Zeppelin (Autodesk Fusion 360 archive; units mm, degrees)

design "Zeppelin" references "Gemfan Hurricane 51466", "TURNIGY_1811"
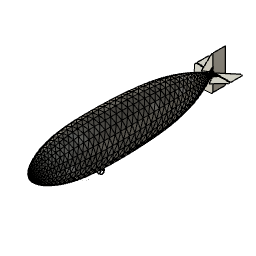
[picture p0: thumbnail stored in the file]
parameter "untereSeiteDreieck" = 220
parameter "kleinerSchnittDreieck" = 18.3138
parameter "untereKante" = 220
base_mesh_feature "Grundnetzelement2"
convert_mesh "Netz konvertieren2" bodies "Envelope"
base_mesh_feature "Grundnetzelement3"
convert_mesh "Netz konvertieren3"
base_mesh_feature "Grundnetzelement4"
convert_mesh "Netz konvertieren4" bodies "Motorhalterung 1"
base_mesh_feature "Grundnetzelement5"
convert_mesh "Netz konvertieren5" bodies "Motorhalterung 2"
base_mesh_feature "Grundnetzelement6"
convert_mesh "Netz konvertieren6" bodies "CFK Connector Vorne"
sketch "Skizze3" plane through (0, 0, 0) normal (1, 0, 0) x axis (0, 1, 0)
  line L1 (0, -276.3) -> (0, -276.5)
  arc A1 centre (-367.7637, 12.4238) radius 430.2363 clockwise from (-307, -413.5) to (-706.3403, -253.0365)
  point P4 (-706.3403, -253.0365)
  point P5 (-307, -413.5)
  vertical L1
  dimension "d6" distance P4 P5 = 430.3733
move "Verschieben4"
work_plane "Arbeitsebene"
sketch "Skizze4" plane through (-63.2811, -308.4675, -275.8442) normal (0.8958, 0.164, 0.413) x axis (-0.1801, 0.9836, 0)
  arc A1 centre (-148.0381, 955.7619) radius 967.1588 clockwise from (0, 0) to (-400, 22)
  point P1 (0, 0)
  point P2 (0, 0)
  coincident P1 P2
pipe "Leitung2" SectionSize 1 SectionThickness 0.25 bodies "CFK Motor Oben 1"
pipe "Leitung3" SectionSize 1 SectionThickness 0.25 bodies "CFK Motor Unten"
mirror "Spiegeln" mirrorStitchTolerance 0.1 bodies "CFK Motor Oben 2"
component_insert "Komponente einfügen1"
component_insert "Komponente einfügen2"
base_mesh_feature "Grundnetzelement8"
convert_mesh "Netz konvertieren7" bodies "ruderhalter_2"
base_mesh_feature "Grundnetzelement9"
convert_mesh "Netz konvertieren8"
move "Verschieben5"
move "Verschieben6"
base_mesh_feature "Grundnetzelement10"
convert_mesh "Netz konvertieren9" bodies "ruderhorn"
base_mesh_feature "Grundnetzelement11"
convert_mesh "Netz konvertieren10" bodies "rudergelenk"
copy_paste_bodies "Körper kopieren/einfügen1"
move "Verschieben7"
copy_paste_bodies "Körper kopieren/einfügen2"
move "Verschieben8"
copy_paste_bodies "Körper kopieren/einfügen3"
move "Verschieben9"
sketch "Skizze5" plane through (0, 0, 0) normal (1, 0, 0) x axis (0, 1, 0)
  line L1 (1250.7758, -2.2569) -> (1250.7758, 0.2431)
  circle C1 centre (1250.7758, -1.0069) radius 1.25
  point P4 (1250.7758, -1.0069)
  point P3 (1250.7758, -2.2569)
  vertical L1
  midpoint L1 P4
  coincident P3 C1
extrude "Extrusion1" new body sketch "Skizze5" distance 200 bodies "CFK Ruderhalter_2"
sketch "Skizze6" plane through (0, 0, -2.5169) normal (0, 0, 1) x axis (-1, 0, 0)
  line L1 (11.8094, -1246.2725) -> (41.4821, -1194.878)
  line L2 (251.951, -1246.2725) -> (11.8094, -1246.2725)
  line L3 (18, -1246.2725) -> (80, -1246.2725)
  line L4 (101.8095, -1090.3879) -> (11.8094, -1246.2725)
  line L5 (218, -1246.2725) -> (11.8094, -1246.2725)
  line L6 (101.8095, -1090.3879) -> (251.951, -1246.2725)
  line L7 (-35, -1218.4724) -> (-32.9972, -1218.4724)
  line L8 (-35, -1213.6225) -> (-35, -1218.4724)
  line L9 (-41, -1213.6225) -> (-35, -1213.6225)
  line L10 (-41, -1218.4724) -> (-41, -1213.6225)
  line L11 (-44.5, -1218.4724) -> (-41, -1218.4724)
  line L12 (-44.5, -1224.7646) -> (-44.5, -1218.4724)
  line L13 (-45, -1225.3606) -> (-44.5, -1224.7646)
  line L14 (-52, -1225.3606) -> (-45, -1225.3606)
  line L15 (-52, -1246.2725) -> (-52, -1225.3606)
  line L16 (-251.9509, -1246.2725) -> (-52, -1246.2725)
  line L17 (-101.8096, -1090.388) -> (-27.8597, -1218.4724)
  line L18 (-251.9509, -1246.2725) -> (-101.8096, -1090.388)
  line L19 (-52, -1225.3606) -> (-45, -1225.3606)
  line L20 (-45, -1225.3606) -> (-44.5, -1224.7646)
  line L21 (-44.5, -1218.4724) -> (-41, -1218.4724)
  line L22 (-41, -1213.6225) -> (-35, -1213.6225)
  line L23 (-35, -1218.4724) -> (-27.8597, -1218.4724)
  line L24 (-41.4821, -1194.878) -> (-27.8597, -1218.4724)
  line L25 (-80, -1246.2725) -> (-52, -1246.2725)
  line L26 (200, -1249.5258) -> (200, -1252.0258)
  line L27 (-200, -1252.0258) -> (-200, -1249.5258)
  line L28 (-200, -1249.5258) -> (200, -1249.5258)
  line L29 (-44.5, -1218.4724) -> (-44.5, -1224.7646)
  line L30 (-41, -1213.6225) -> (-41, -1218.4724)
  line L31 (-35, -1213.6225) -> (-35, -1218.4724)
  line L32 (-231.8093, -1254.8215) -> (-11.8093, -1254.8215)
  line L33 (-231.8093, -1414.8215) -> (-231.8093, -1254.8215)
  line L34 (-27.8597, -1218.4724) -> (-11.8093, -1246.2725)
  line L35 (-11.8093, -1246.2725) -> (-52, -1246.2725)
  line L36 (-231.8093, -1225.3605) -> (-231.8093, -1246.2725)
  line L37 (231.8094, -1225.3605) -> (231.8094, -1246.2725)
  line L38 (-44.4083, -1254.8215) -> (-41.4083, -1254.8215)
  line L39 (-231.8093, -1414.8215) -> (-199.7764, -1414.8215)
  line L40 (-11.8093, -1254.8215) -> (-199.7764, -1414.8215)
  line L41 (0, -20) -> (0, -2.5)
  line L42 (231.8093, -1254.8215) -> (11.8093, -1254.8215)
  line L43 (231.8093, -1414.8215) -> (231.8093, -1254.8215)
  line L44 (11.8093, -1254.8215) -> (199.7764, -1414.8215)
  line L45 (231.8093, -1414.8215) -> (199.7764, -1414.8215)
  point P3 (11.8094, -1246.2725)
  point P4 (11.8094, -1246.2725)
  point P21 (-27.8597, -1218.4724)
  point P22 (-101.8096, -1090.388)
  point P23 (-251.9509, -1246.2725)
  point P37 (200, -1249.5258)
  point P40 (200, -1249.5258)
  point P38 (-200, -1249.5258)
  point P41 (-200, -1249.5258)
  point P20 (-251.9509, -1246.2725)
  point P31 (-27.8597, -1218.4724)
  point P46 (-27.8597, -1218.4724)
  point P45 (-11.8093, -1246.2725)
  point P34 (-52, -1246.2725)
  point P47 (-52, -1246.2725)
  point P48 (-231.8093, -1246.2725)
  point P49 (-231.8093, -1225.3605)
  point P50 (231.8094, -1246.2725)
  point P51 (231.8094, -1225.3605)
  point P42 (-11.8093, -1254.8215)
  point P43 (-231.8093, -1254.8215)
  point P52 (-231.8093, -1254.8215)
  point P58 (11.8093, -1254.8215)
  point P60 (231.8093, -1254.8215)
  point P44 (-231.8093, -1414.8215)
  point P61 (231.8093, -1414.8215)
  point P59 (231.8093, -1254.8215)
  point P55 (-199.7764, -1414.8215)
  point P62 (199.7764, -1414.8215)
  point P8 (101.8095, -1090.3879)
  point P18 (-52, -1225.3606)
  point P19 (-52, -1246.2725)
  coincident P3 P4
  collinear L2 L3
  horizontal L5
  horizontal L7
  horizontal L9
  horizontal L14
  coincident L7 P21
  coincident L17 P22
  coincident L16 P23
  collinear L14 L19
  collinear L13 L20
  collinear L11 L21
  collinear L9 L22
  collinear L7 L23
  collinear L17 L24
  collinear L16 L25
  coincident P37 P40
  coincident P38 P41
  coincident P20 P23
  collinear L12 L29
  collinear L10 L30
  collinear L8 L31
  parallel L28 L32
  vertical L33
  coincident P31 P46
  horizontal P4 P45
  coincident P34 P47
  perpendicular L15 L35
  collinear L1 L4
  coincident L16 P48
  coincident L18 P49
  perpendicular L16 L36
  coincident L2 P50
  coincident L6 P51
  perpendicular L2 L37
  vertical P42 P45
  collinear L32 L38
  coincident P43 P52
  perpendicular L33 L39
  symmetric P42 L41 P58
  symmetric P43 L41 P60
  symmetric P44 L41 P61
  symmetric P52 L41 P59
  symmetric P55 L41 P62
  dimension "LinkeSeiteUnten" distance P43 P44 = 160
  dimension "d55" angle L17 L34 = 180
  dimension "eineSeiteDreieck" distance P22 P45 = 180
  dimension "d61" distance P4 P8 = 180 (= "eineSeiteDreieck")
  dimension "d71" distance P45 L36 = 220 (= "untereKante")
  dimension "AbschnittDreieck" distance P48 P49 = 20.912
  dimension "d74" distance P4 L37 = 220 (= "untereKante")
  dimension "d75" distance P50 P51 = 20.912 (= "AbschnittDreieck")
  dimension "d76" distance P18 P19 = 20.9119
  dimension "d77" distance P42 P52 = 220 (= "untereKante")
  dimension "d78" distance P44 P55 = 32.0329
extrude "Extrusion2" new body sketch "Skizze6" profile of L1 L2 L3 L4 L6 L7 L8 L9 L10 L11 L12 L13 L14 L15 L16 L17 L18 L19 L20 L21 L22 L23 L24 L25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 along normal blind 3 bodies "Depron R2-L", "Depron R2-R"
sketch "Skizze7" plane through (-3, 0, 0) normal (1, 0, 0) x axis (0, 1, 0)
  line L1 (1241.7614, 232.081) -> (1241.7614, 12.081)
  line L2 (1085.8768, 102.081) -> (1241.7614, 12.081)
  line L3 (1231.039, 18.2716) -> (1190.3668, 41.7537)
  line L4 (1241.7614, 18.2716) -> (1241.7614, 80.2716)
  line L5 (1220.8494, 232.081) -> (1241.7614, 232.081)
  line L6 (1085.8768, 102.081) -> (1220.8494, 232.081)
  line L7 (22.5, 0) -> (1.75, 0)
  line L8 (1220.8494, -232.081) -> (1241.7614, -232.081)
  line L9 (1085.8768, -102.081) -> (1220.8494, -232.081)
  line L10 (1241.7614, -232.081) -> (1241.7614, -12.081)
  line L11 (1085.8768, -102.081) -> (1241.7614, -12.081)
  line L12 (1241.7614, 80.2716) -> (1237.7614, 19.0092)
  line L13 (1237.7614, 72.2751) -> (1241.7614, 80.2716)
  line L14 (1237.7614, 19.0092) -> (1237.7614, 72.2751)
  line L15 (1414.7614, 232.081) -> (1244.7614, 232.081)
  line L16 (1414.7614, -232.081) -> (1414.7614, 232.081)
  line L17 (1244.7614, -232.081) -> (1244.7614, 232.081)
  line L18 (1414.7614, -232.081) -> (1244.7614, -232.081)
  line L19 (1258, -50.7284) -> (1244.7614, -50.7284)
  line L20 (1258, 12.081) -> (1258, -50.7284)
  line L21 (1244.7614, 12.081) -> (1258, 12.081)
  point P2 (1241.7614, 12.081)
  point P15 (1241.7614, -12.081)
  point P3 (1241.7614, 232.081)
  point P12 (1241.7614, -232.081)
  point P4 (1085.8768, 102.081)
  point P14 (1085.8768, -102.081)
  point P9 (1220.8494, 232.081)
  point P13 (1220.8494, -232.081)
  point P21 (1414.7614, -232.081)
  point P19 (1244.7614, 232.081)
  point P23 (1244.7614, -50.7284)
  point P26 (1244.7614, 12.081)
  point P27 (1237.7614, -50.7284)
  point P20 (1414.7614, 232.081)
  point P24 (1258, -50.7284)
  vertical L1
  collinear L2 L3
  collinear L1 L4
  perpendicular L1 L5
  symmetric P2 L7 P15
  symmetric P3 L7 P12
  symmetric P4 L7 P14
  symmetric P9 L7 P13
  perpendicular L1 L15
  perpendicular L15 L16
  horizontal P12 P21
  horizontal P3 P19
  perpendicular L15 L17
  perpendicular L17 L18
  coincident L17 P23
  perpendicular L17 L19
  perpendicular L19 L20
  coincident L17 P26
  perpendicular L17 L21
  horizontal P23 P27
  horizontal P2 P26
  dimension "d79" distance P2 P3 = 220 (= "untereKante")
  dimension "d80" distance P2 P4 = 180 (= "eineSeiteDreieck")
  dimension "d81" distance P3 P9 = 20.912 (= "AbschnittDreieck")
  dimension "kurzeSeiteViereck" distance P19 P20 = 170
  dimension "d85" distance P3 P19 = 3
  dimension "servolaenge" distance P23 P24 = 13.2386
extrude "Extrusion3" new body sketch "Skizze7" profile of L1 L2 L3 L4 L5 L6 L8 L9 L10 L11 L15 L16 L17 L18 L19 L20 L21 along normal blind 3
move "Verschieben10"
extrude "Extrusion4" add of existing geometry blind 0.2
extrude "Extrusion5" add of existing geometry blind 0.2
extrude "Extrusion6" add of existing geometry blind 0.6
extrude "Extrusion7" cut of existing geometry blind -0.4
extrude "Extrusion8" add of existing geometry blind 2
offset_faces "Flächen versetzen" distance -0.3
extrude "Extrusion10" add of existing geometry blind 0.2
extrude "Extrusion11" add of existing geometry blind 0.2
extrude "Extrusion12" add of existing geometry blind 0.2
extrude "Extrusion13" add of existing geometry blind 0.2
extrude "Extrusion14" add of existing geometry blind 0.6
extrude "Extrusion15" cut of existing geometry blind -0.4
move_face "Fläche verschieben1" RotateAngle -5
extrude "Extrusion18" add of existing geometry blind 2.6
extrude "Extrusion19" add of existing geometry blind 2.6
move_face "Fläche verschieben2"
extrude "Extrusion20" add of existing geometry blind 3
extrude "Extrusion21" cut of existing geometry blind -2.6
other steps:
base_feature "Basiselement2" bodies "rudergelenk", "rudergelenk (1)"
base_feature "Basiselement3" bodies "rudergelenk (1)", "rudergelenk (1) (1)"
base_feature "Basiselement4" bodies "rudergelenk (2)"
named bodies: "Envelope", "Motorhalterung 1", "Motorhalterung 2", "CFK Connector Vorne", "CFK Motor Oben 1", "CFK Motor Unten", "CFK Motor Oben 2", "ruderhalter_2", "ruderhalter_1", "CFK Ruderhalter_2", "Depron R2-L", "Depron R2-R", "ruderhorn", "rudergelenk", "rudergelenk (1)", "rudergelenk (1) (1)", "rudergelenk (2)"

design "Gemfan Hurricane 51466"
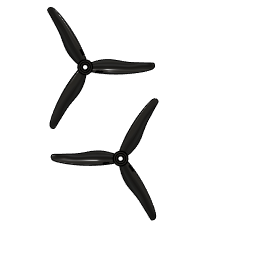
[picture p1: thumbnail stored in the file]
sketch "Sketch1" plane through (0, 0, 0) normal (0, 1, 0) x axis (1, 0, 0)
  curve K1 (5.4694, -4.0404) -> (5.1621, 4.4263)
  curve K2 (26.4739, 6.387) -> (10.3147, 5.303)
  curve K3 (55.5282, 3.9374) -> (37.5729, 6.2078)
  curve K4 (23.3421, -7.4304) -> (38.5067, -4.4448)
  curve K5 (7.6655, -5.2742) -> (22.2218, -7.6881)
  curve K6 (52.69, -3.7559) -> (67.3074, -3.2468)
  curve K7 (66.947, -7.3026) -> (59.4681, 7.5356)
  curve K8 (66.2975, -0.0581) -> (55.4147, 4.071)
  line L1 (78.7648, 0) -> (0, 0)
  curve K9 (61.3404, -6.2574) -> (65.9163, 0.3238)
  curve K10 (8.9395, 5.261) -> (1.3848, 3.5917)
  circle C1 centre (0, 0) radius 6.8
  circle C2 centre (0, 0) radius 2.5
  point P1 (0, 0)
  point P2 (0, 0)
  point P3 (0, 0)
  point P4 (5.1621, 4.4263)
  point P14 (5.4694, -4.0404)
  point P5 (18.3943, 5.845)
  point P6 (46.5505, 5.0726)
  point P12 (30.9244, -5.9376)
  point P13 (14.9437, -6.4811)
  point P10 (59.9987, -3.5013)
  point P8 (63.2076, 0.1165)
  point P7 (60.8561, 2.0065)
  point P29 (0, 0)
  point P9 (63.6284, -2.9668)
  coincident P1 P2
  coincident P1 P3
  coincident C1 P4
  coincident C1 P14
  midpoint P5 K2
  midpoint P6 K3
  midpoint P12 K4
  midpoint P13 K5
  midpoint P10 K6
  midpoint P8 K7
  midpoint P7 K8
  coincident P1 P29
  midpoint P9 K9
  midpoint P4 K10
  dimension "d1" diameter C1 = 13.6
  dimension "d2" diameter C2 = 5
extrude "Extrude1" new body sketch "Sketch1" profile of C1 C2 distance 7
work_plane "WorkPlane6" AlongDistance 4.5
sketch "Sketch3" plane through (4.5, 0, 0) normal (1, 0, 0) x axis (0, 0, -1)
  line L1 (6.8, -3.5) -> (-6.8, -3.5)
  line L2 (-6.8, 3.5) -> (6.8, 3.5)
  line L3 (4, -3.5) -> (4, 3.5)
  line L4 (-3.75, -3.5) -> (-3.75, 3.5)
  curve K1 (-3.75, -3.1239) -> (-3.75, -3.1239)
  curve K2 (-3.5611, -3.317) -> (-3.9389, -2.9308)
  curve K3 (0.2448, -0.7564) -> (-2.2448, -2.2436)
  curve K4 (-3.5886, -0.8664) -> (-0.9748, 1.9804)
  curve K5 (3.4341, 3.3087) -> (4.5659, 2.0069)
  curve K6 (0.0208, 2.5606) -> (2.6178, 3.2817)
  point P7 (4, 3.5)
  point P9 (-3.75, 3.5)
  point P11 (-3.75, -3.1239)
  point P14 (4, 2.6578)
  point P12 (-1, -1.5)
  point P16 (-2.2817, 0.557)
  point P15 (1.3193, 2.9212)
  point P1 (0, 0)
  vertical L3
  coincident L2 P7
  vertical L4
  coincident L2 P9
  coincident L4 P11
  coincident L3 P14
  midpoint P11 K2
  midpoint P12 K3
  midpoint P16 K4
  midpoint P14 K5
  midpoint P15 K6
  dimension "d15" distance P1 L3 = 4
  dimension "d17" distance P1 L4 = 3.75
work_plane "WorkPlane4" AlongDistance 22
sketch "Sketch5" plane through (22, 0, 0) normal (1, 0, 0) x axis (0, 0, -1)
  line L1 (6.0622, 0) -> (-7.0278, 0)
  curve K1 (-4.0404, 0) -> (4.4263, 0)
  line L2 (-7.0278, -3) -> (-7.0278, 0)
  line L3 (6.0622, 3.7) -> (6.0622, 0)
  curve K2 (-7.0278, -3) -> (-7.0278, -3)
  curve K3 (-6.9778, -3.0682) -> (-7.0777, -2.9318)
  point P4 (0, 0)
  point P2 (-7.0278, 0)
  point P7 (-7.0278, -3)
  horizontal L1
  coincident L1 P4
  coincident P2 K1
  perpendicular L1 L2
  midpoint P7 K3
sketch "Sketch8" plane through (22, 0, 0) normal (1, 0, 0) x axis (0, 0, -1)
  curve K1 (-2.9668, 0) -> (-3.75, -3.1239)
  curve K2 (-4.0148, -0.0865) -> (-4.1879, -1.0525)
  curve K3 (0.1695, 0.6998) -> (-6.1031, -0.6998)
  curve K4 (-2.9668, 0) -> (4, 2.6578)
  point P2 (-3.75, -3.1239)
  point P5 (-3.75, -3.1239)
  point P3 (-7.0278, -3)
  point P6 (-7.0278, -3)
  point P4 (-2.9668, 0)
  point P7 (-2.9668, 0)
  point P10 (-4.1014, -0.5695)
  point P9 (4, 2.6578)
  point P17 (4, 2.6578)
  point P8 (6.0622, 3.7)
  point P18 (6.0622, 3.7)
  coincident P2 P5
  coincident P3 P6
  coincident P4 P7
  midpoint P10 K2
  midpoint P4 K3
  coincident P9 P17
  coincident P8 P18
loft "Loft1" sketch "Sketch3" + "Sketch5"
sketch "Sketch20" plane through (0, 0, 0) normal (0, 0, 1) x axis (1, 0, 0)
  curve K1 (63.6284, 0) -> (4.5, 2.6578)
  curve K2 (63.6284, 0) -> (4.5, -3.1239)
  line L1 (4.5, -3.1239) -> (4.5, 2.6578)
  curve K3 (63.832, 0.4996) -> (4.5, 2.6578)
  curve K4 (23.1023, 5.0891) -> (6.2355, 3.4227)
  curve K5 (5.6102, 3.6045) -> (3.3898, 1.711)
  curve K6 (32.3804, 4.5964) -> (22.8999, 4.8276)
  curve K7 (64.042, 1.479) -> (50.2693, 3.2872)
  curve K8 (64.0517, -0.4301) -> (63.6123, 1.4292)
  line L2 (6.8, -3.5) -> (-6.8, -3.5)
  line L3 (-6.8, 3.5) -> (6.8, 3.5)
  line L4 (6.8, 3.3093) -> (6.8, 3.5)
  line L5 (6.8, -3.5) -> (6.8, -3.2734)
  line L6 (0, 3.5) -> (0, -3.5)
  line L7 (6.8, -3.5) -> (0, -3.5)
  line L8 (0, 3.5) -> (6.8, 3.5)
  point P2 (4.5, 2.6578)
  point P6 (4.5, 2.6578)
  point P4 (4.5, -3.1239)
  point P7 (4.5, -3.1239)
  point P8 (4.5, 2.6578)
  point P12 (63.832, 0.4996)
  point P9 (14.6689, 4.2559)
  point P10 (27.6402, 4.712)
  point P11 (57.1557, 2.3831)
  point P25 (6.8, 3.5)
  point P27 (6.8, 3.5)
  point P28 (6.8, 3.3093)
  point P29 (6.8, -3.2734)
  point P24 (6.8, -3.5)
  point P30 (6.8, -3.5)
  point P1 (0, 0)
  point P31 (0, -3.5)
  point P33 (6.8, 3.5)
  coincident P2 P6
  coincident P4 P7
  coincident P6 P8
  coincident K1 P12
  midpoint P9 K4
  midpoint P8 K5
  midpoint P10 K6
  midpoint P11 K7
  midpoint P12 K8
  coincident P25 P27
  coincident K3 P28
  perpendicular L3 L4
  coincident K2 P29
  coincident P24 P30
  perpendicular L2 L5
  perpendicular L2 L6
  midpoint P1 L6
  midpoint L2 P31
  coincident P25 P33
revolve "Revolve1" sketch "Sketch20" AlongAngle 360
circular_pattern "C-Pattern1" TotalAngle 360
combine "Combine1"
fillet "Fillet1" radius 0.15 0.2 0.2
chamfer "Chamfer1" distance 1
sketch "Sketch9" plane through (0, 3.5, 0) normal (0, 1, 0) x axis (-1, 0, 0)
  line L1 (2.4871, -1.6776) -> (0, 0)
  line L2 (2.3103, -0.9552) -> (1.7511, -1.7843)
  line L3 (3, 0) -> (0, 0)
  curve K1 (1.8074, 6.3477) -> (-0.2661, 6.5946)
  curve K2 (-6.401, -1.6086) -> (-5.5781, -3.5277)
  curve K3 (4.5936, -4.7391) -> (5.8442, -3.0669)
  circle C1 centre (0, 0) radius 2.5
  circle C2 centre (0, 0) radius 4.75
  circle C3 centre (0, 0) radius 2.5
  circle C4 centre (0, 0) radius 3
  arc A1 centre (2.0707, -1.3967) radius 0.5023 clockwise from (2.3103, -0.9552) to (1.7511, -1.7843)
  arc A2 centre (0, 0) radius 6.6 clockwise from (1.8074, 6.3477) to (5.8442, -3.0669)
  arc A3 centre (0, 0) radius 6.6 clockwise from (-6.401, -1.6086) to (-0.2661, 6.5946)
  arc A4 centre (0, 0) radius 6.6 clockwise from (4.5936, -4.7391) to (-5.5781, -3.5277)
  point P1 (0, 0)
  point P3 (0, 0)
  point P4 (0, 0)
  point P6 (0, 0)
  point P7 (2.4871, -1.6776)
  point P9 (2.3103, -0.9552)
  point P8 (1.7511, -1.7843)
  point P11 (2.0307, -1.3697)
  point P12 (0, 0)
  point P13 (3, 0)
  coincident P1 P3
  concentric C3 C4
  coincident P4 P6
  coincident C4 P7
  coincident P7 A1
  tangent C4 A1
  coincident C1 P9
  coincident C1 P8
  coincident L1 P11
  perpendicular L1 L2
  midpoint P11 L2
  coincident P1 P12
  coincident C4 P13
  horizontal L3
  dimension "d24" diameter C2 = 9.5
  dimension "d25" diameter C4 = 6
  dimension "d26" distance P8 P9 = 1
  dimension "d35" angle L1 L3 = 34
move "Move1" TranslateX 0 TranslateY -0.025 TranslateZ 0
extrude "Extrude2" add sketch "Sketch9" profile of C1 C2 C3 C4 L1 A1 to an object
chamfer "Chamfer2" distance 0.5
extrude "Extrude3" cut sketch "Sketch9" profile of C1 C3 A1 L2 against normal blind 2
circular_pattern "C-Pattern2" TotalAngle 360
fillet "Fillet2" radius 0.1
fillet "Fillet3" radius 0.1
work_plane "WorkPlane7" AlongDistance 8
sketch "Gemfan Logo" plane through (0, 0, 0) normal (0, 1, 0) x axis (1, 0, 0)
  curve K1 (-21.8749, -5.831) -> (-20.1359, 0.6002)
  curve K2 (-24.28, -4.52) -> (-20.6611, -1.3859)
  curve K3 (-23.3443, -4.4717) -> (-25.2158, -4.5684)
  line L1 (-21.0026, -2.6965) -> (-21.8749, -5.831)
  line L2 (-23.7916, -2.6965) -> (-21.0026, -2.6965)
  line L3 (-24.28, -4.52) -> (-23.7916, -2.6965)
  line L4 (-20.6611, -1.3859) -> (-20.1359, 0.6002)
  line L5 (-12.3656, 0.8894) -> (-19.4089, 0.8894)
  curve K4 (28.4771, 4.595) -> (-20.955, -5.8616)
  curve K5 (33.0602, 3.9357) -> (23.894, 5.2543)
  curve K6 (-17.2888, -2.7107) -> (-24.6212, -9.0126)
  curve K7 (25.1622, 1.9813) -> (-20.955, -5.8616)
  line L6 (25.1622, 1.9813) -> (28.4771, 4.595)
  curve K8 (-17.694, -3.4791) -> (-24.2161, -8.2442)
  curve K9 (28.6113, 1.0913) -> (21.713, 2.8713)
  line L7 (-21.2476, -5.8041) -> (-19.4089, 0.8894)
  line L8 (-17.3535, -2.0106) -> (-17.1389, -1.1922)
  line L9 (-16.7225, -2.0106) -> (-17.3535, -2.0106)
  line L10 (-15.8, -1.1922) -> (-17.1389, -1.1922)
  curve K10 (-16.7225, -2.0106) -> (-21.2476, -5.8041)
  curve K11 (-16.0902, -1.5693) -> (-17.3548, -2.4519)
  curve K12 (-12.3656, 0.8894) -> (-15.8, -1.1922)
  curve K13 (-11.9871, 1.0819) -> (-12.7441, 0.6969)
  line L11 (-14.3976, -5.927) -> (-20.4864, -5.927)
  line L12 (-13.9738, -4.1566) -> (-14.3976, -5.927)
  line L13 (-17.6773, -4.1566) -> (-13.9738, -4.1566)
  line L14 (-20.4864, -5.927) -> (-17.6773, -4.1566)
  line L15 (-13.7968, -3.4173) -> (-16.2424, -3.4173)
  line L16 (-13.4588, -2.0058) -> (-13.7968, -3.4173)
  line L17 (-16.2424, -3.4173) -> (-13.4588, -2.0058)
  line L18 (-13.8215, -5.927) -> (-12.7833, -1.7405)
  line L19 (-11.1054, -5.927) -> (-13.8215, -5.927)
  line L20 (-10.1204, -1.9546) -> (-11.1054, -5.927)
  line L21 (-9.7695, -5.9089) -> (-10.1204, -1.9546)
  line L22 (-8.1269, -5.9089) -> (-9.7695, -5.9089)
  line L23 (-5.7331, -2.13) -> (-8.1269, -5.9089)
  line L24 (-6.7309, -5.9089) -> (-5.7331, -2.13)
  line L25 (-4.0148, -5.9089) -> (-6.7309, -5.9089)
  line L26 (-2.2198, 0.8894) -> (-4.0148, -5.9089)
  line L27 (-5.5252, 0.8894) -> (-2.2198, 0.8894)
  line L28 (-8.1349, -2.7437) -> (-5.5252, 0.8894)
  line L29 (-8.3619, -0.1859) -> (-8.1349, -2.7437)
  line L30 (-8.3619, -0.1859) -> (-12.7833, -1.7405)
  line L31 (-3.3335, -5.9313) -> (-1.5326, 0.8894)
  line L32 (-0.5052, -5.9313) -> (-3.3335, -5.9313)
  line L33 (-0.0707, -4.2859) -> (-0.5052, -5.9313)
  line L34 (3.778, -4.2859) -> (-0.0707, -4.2859)
  line L35 (4.3561, -2.0964) -> (3.778, -4.2859)
  line L36 (0.4746, -2.0964) -> (4.3561, -2.0964)
  line L37 (0.6849, -1.3001) -> (0.4746, -2.0964)
  line L38 (4.5664, -1.3001) -> (0.6849, -1.3001)
  line L39 (5.1445, 0.8894) -> (4.5664, -1.3001)
  line L40 (-1.5326, 0.8894) -> (5.1445, 0.8894)
  line L41 (7.4604, 0.8894) -> (3.2005, -5.9313)
  line L42 (12.0969, 0.8894) -> (7.4604, 0.8894)
  line L43 (12.0969, -5.9313) -> (12.0969, 0.8894)
  line L44 (9.2568, -5.9313) -> (12.0969, -5.9313)
  line L45 (9.2568, -4.9008) -> (9.2568, -5.9313)
  line L46 (6.9418, -4.9008) -> (9.2568, -4.9008)
  line L47 (6.2983, -5.9313) -> (6.9418, -4.9008)
  line L48 (3.2005, -5.9313) -> (6.2983, -5.9313)
  line L49 (9.3263, -3.2639) -> (7.7788, -3.2639)
  line L50 (9.3263, -0.7861) -> (9.3263, -3.2639)
  line L51 (7.7788, -3.2639) -> (9.3263, -0.7861)
  line L52 (17.3328, 0.8894) -> (14.2439, 0.8894)
  line L53 (18.2037, -3.0583) -> (17.3328, 0.8894)
  line L54 (19.2029, 0.8894) -> (18.2037, -3.0583)
  line L55 (22.2157, 0.8894) -> (19.2029, 0.8894)
  line L56 (20.4893, -5.9313) -> (22.2157, 0.8894)
  line L57 (17, -5.9313) -> (20.4893, -5.9313)
  line L58 (15.2595, -5.9313) -> (16.1894, -2.2572)
  line L59 (12.5176, -5.9313) -> (15.2595, -5.9313)
  line L60 (14.2439, 0.8894) -> (12.5176, -5.9313)
  line L61 (17, -5.9313) -> (16.1894, -2.2572)
  point P14 (-24.28, -4.52)
  point P24 (28.4771, 4.595)
  point P21 (-20.955, -5.8616)
  point P31 (25.1622, 1.9813)
  point P39 (-16.7225, -2.0106)
  point P20 (-12.3656, 0.8894)
  midpoint P14 K3
  horizontal L2
  horizontal L5
  midpoint P24 K5
  midpoint P21 K6
  midpoint P21 K8
  midpoint P31 K9
  horizontal L9
  horizontal L10
  midpoint P39 K11
  midpoint P20 K13
  collinear L12 L16
  horizontal L13
  horizontal L15
  parallel L18 L20
  horizontal L25
  parallel L24 L26
  parallel L25 L27
  horizontal L19
  horizontal L22
  parallel L21 L29
  equal L23 L28
  collinear L11 L19
  collinear L22 L25
  parallel L26 L31
  horizontal L32
  parallel L31 L33
  parallel L32 L34
  parallel L31 L35
  parallel L34 L36
  parallel L35 L37
  parallel L34 L38
  collinear L35 L39
  horizontal L40
  equal L35 L39
  equal L19 L25
  horizontal L42
  perpendicular L42 L43
  perpendicular L43 L44
  perpendicular L44 L45
  perpendicular L45 L46
  parallel L48 L49
  perpendicular L48 L50
  horizontal L48
  collinear L32 L48
  collinear L44 L48
  parallel L41 L51
  parallel L47 L51
  collinear L40 L42
  collinear L27 L40
  collinear L5 L27
  horizontal L52
  parallel L54 L56
  parallel L52 L57
  parallel L54 L58
  parallel L57 L59
  parallel L58 L60
  collinear L44 L59
  collinear L57 L59
  collinear L42 L52
  collinear L52 L55
  parallel L53 L61
work_plane "WorkPlane8" AlongDistance 10
mirror "Mirror2"
sketch "GEMFAN" plane through (28.9566, 10, -18.6867) normal (0, 1, 0) x axis (1, 0, 0)
  line L1 (-18.9529, -15.1247) -> (-18.6056, -15.0943)
  line L2 (-18.5773, -14.9274) -> (-18.5336, -14.6743)
  line L3 (-17.5691, -14.5537) -> (-18.4462, -14.6304)
  line L4 (-18.1586, -14.9691) -> (-18.1408, -14.8649)
  curve K1 (-18.68, -15.4941) -> (-18.5336, -14.6743)
  curve K2 (-12.5236, -13.6473) -> (-18.5652, -15.4879)
  line L5 (-12.9079, -14.0089) -> (-12.5236, -13.6473)
  curve K3 (-12.9079, -14.0089) -> (-18.5652, -15.4879)
  line L6 (-17.9741, -14.8503) -> (-18.1408, -14.8649)
  curve K4 (-18.0801, -14.9623) -> (-18.6022, -15.484)
  curve K5 (-18.9938, -15.3571) -> (-18.5773, -14.9274)
  line L7 (-18.9938, -15.3571) -> (-18.9529, -15.1247)
  line L8 (-18.6022, -15.484) -> (-18.4462, -14.6304)
  line L9 (-17.2585, -14.8834) -> (-17.1718, -15.372)
  line L10 (-16.0179, -15.2738) -> (-15.9817, -15.0642)
  line L11 (-14.2556, -14.2638) -> (-13.8709, -14.2301)
  line L12 (-15.4543, -14.7433) -> (-15.9377, -14.7856)
  line L13 (-15.5025, -15.0223) -> (-15.4543, -14.7433)
  line L14 (-15.5564, -15.2334) -> (-15.1003, -14.3377)
  line L15 (-14.3962, -15.1319) -> (-14.2556, -14.2638)
  line L16 (-14.0548, -15.1021) -> (-14.3962, -15.1319)
  line L17 (-17.0588, -14.644) -> (-17.5925, -14.8857)
  line L18 (-16.3701, -15.3046) -> (-16.0179, -15.2738)
  line L19 (-13.2629, -14.1769) -> (-13.4036, -15.0451)
  line L20 (-17.5925, -14.8857) -> (-17.6761, -15.4184)
  line L21 (-17.0027, -14.96) -> (-17.0588, -14.644)
  line L22 (-15.4368, -14.6419) -> (-15.3887, -14.3629)
  line L23 (-18.5061, -15.491) -> (-17.7479, -15.4246)
  line L24 (-15.3887, -14.3629) -> (-16.2201, -14.4357)
  curve K6 (-17.5691, -14.5537) -> (-17.9741, -14.8503)
  line L25 (-17.6737, -14.9261) -> (-18.0049, -15.1322)
  line L26 (-18.6056, -15.0943) -> (-18.68, -15.4941)
  line L27 (-17.7479, -15.4246) -> (-17.7144, -15.1995)
  line L28 (-16.9672, -15.3541) -> (-16.7103, -14.8574)
  line L29 (-18.0801, -14.9623) -> (-18.1586, -14.9691)
  line L30 (-14.8135, -15.0391) -> (-15.1018, -15.0644)
  line L31 (-14.8023, -15.1675) -> (-14.8135, -15.0391)
  line L32 (-15.0154, -14.8514) -> (-14.8227, -14.8345)
  line L33 (-13.6381, -14.2098) -> (-13.2629, -14.1769)
  line L34 (-14.8497, -14.526) -> (-15.0154, -14.8514)
  line L35 (-17.7144, -15.1995) -> (-18.1756, -15.2399)
  line L36 (-17.3379, -15.3888) -> (-17.2585, -14.8834)
  line L37 (-15.9377, -14.7856) -> (-15.9202, -14.6841)
  line L38 (-13.8381, -15.0831) -> (-13.979, -14.6344)
  line L39 (-17.6761, -15.4184) -> (-17.3379, -15.3888)
  line L40 (-13.8709, -14.2301) -> (-13.7195, -14.7122)
  line L41 (-15.1018, -15.0644) -> (-15.1707, -15.1997)
  line L42 (-18.0049, -15.1322) -> (-17.7004, -15.1056)
  line L43 (-15.1003, -14.3377) -> (-14.5229, -14.2872)
  line L44 (-15.9202, -14.6841) -> (-15.4368, -14.6419)
  line L45 (-13.7195, -14.7122) -> (-13.6381, -14.2098)
  line L46 (-16.2201, -14.4357) -> (-16.3701, -15.3046)
  line L47 (-15.9817, -15.0642) -> (-15.5025, -15.0223)
  line L48 (-16.7173, -14.4792) -> (-17.0027, -14.96)
  line L49 (-14.4486, -15.1365) -> (-14.8023, -15.1675)
  line L50 (-14.8227, -14.8345) -> (-14.8497, -14.526)
  line L51 (-16.7934, -15.3388) -> (-16.4552, -15.3093)
  line L52 (-16.7103, -14.8574) -> (-16.7934, -15.3388)
  line L53 (-15.1707, -15.1997) -> (-15.5564, -15.2334)
  line L54 (-16.3057, -14.4431) -> (-16.7173, -14.4792)
  line L55 (-17.1718, -15.372) -> (-16.9672, -15.3541)
  line L56 (-18.1756, -15.2399) -> (-18.5061, -15.491)
  line L57 (-17.7004, -15.1056) -> (-17.6737, -14.9261)
  line L58 (-16.4552, -15.3093) -> (-16.3057, -14.4431)
  line L59 (-13.979, -14.6344) -> (-14.0548, -15.1021)
  line L60 (-14.5229, -14.2872) -> (-14.4486, -15.1365)
  line L61 (-13.4036, -15.0451) -> (-13.8381, -15.0831)
extrude "Extrude4" sketch "GEMFAN" blind 0.1 named "d44"
sketch "Sketch13" plane through (0, 10, 0) normal (0, 1, 0) x axis (1, 0, 0)
  curve K1 (-2.5023, -10.96) -> (-2.6532, -11.0269)
  curve K2 (-2.3196, -10.9752) -> (-2.5023, -10.96)
  line L1 (-2.3967, -11.1406) -> (-2.3196, -10.9752)
  curve K3 (-2.5197, -11.1475) -> (-2.3967, -11.1406)
  curve K4 (-2.6082, -11.2435) -> (-2.5197, -11.1475)
  curve K5 (-2.6125, -11.3904) -> (-2.6082, -11.2435)
  curve K6 (-2.4863, -11.5017) -> (-2.6125, -11.3904)
  line L2 (-2.3904, -11.5465) -> (-2.4863, -11.5017)
  curve K7 (-2.224, -11.5715) -> (-2.3904, -11.5465)
  curve K8 (-2.1142, -11.4738) -> (-2.224, -11.5715)
  curve K9 (-2.1002, -11.3811) -> (-2.1142, -11.4738)
  curve K10 (-2.1349, -11.2802) -> (-2.1002, -11.3811)
  line L3 (-2.0644, -11.1292) -> (-2.1349, -11.2802)
  line L4 (-1.4578, -11.4121) -> (-2.0644, -11.1292)
  line L5 (-1.7373, -12.0115) -> (-1.4578, -11.4121)
  line L6 (-1.8908, -11.94) -> (-1.7373, -12.0115)
  line L7 (-1.6884, -11.506) -> (-1.8908, -11.94)
  line L8 (-1.9474, -11.3852) -> (-1.6884, -11.506)
  curve K11 (-1.9414, -11.4726) -> (-1.9474, -11.3852)
  curve K12 (-1.9628, -11.5561) -> (-1.9414, -11.4726)
  curve K13 (-2.0852, -11.7121) -> (-1.9628, -11.5561)
  curve K14 (-2.2565, -11.7665) -> (-2.0852, -11.7121)
  curve K15 (-2.4663, -11.7154) -> (-2.2565, -11.7665)
  line L9 (-2.5622, -11.6707) -> (-2.4663, -11.7154)
  curve K16 (-2.7361, -11.5429) -> (-2.5622, -11.6707)
  curve K17 (-2.8035, -11.3743) -> (-2.7361, -11.5429)
  curve K18 (-2.7604, -11.1754) -> (-2.8035, -11.3743)
  curve K19 (-2.6532, -11.0269) -> (-2.7604, -11.1754)
  line L10 (-3.0818, -11.8897) -> (-3.1589, -12.0551)
  line L11 (-2.1058, -12.3448) -> (-3.0818, -11.8897)
  line L12 (-2.1282, -12.13) -> (-2.1058, -12.3448)
  line L13 (-1.9628, -12.2071) -> (-2.1282, -12.13)
  line L14 (-1.9307, -12.4264) -> (-1.9628, -12.2071)
  line L15 (-2.0079, -12.5919) -> (-1.9307, -12.4264)
  line L16 (-3.1589, -12.0551) -> (-2.0079, -12.5919)
  line L17 (-2.321, -13.2633) -> (-2.971, -12.4785)
  line L18 (-2.4004, -13.4335) -> (-2.321, -13.2633)
  line L19 (-3.0464, -12.6652) -> (-2.4004, -13.4335)
  line L20 (-3.3147, -13.2407) -> (-3.0464, -12.6652)
  line L21 (-3.4634, -13.1714) -> (-3.3147, -13.2407)
  line L22 (-3.1112, -12.416) -> (-3.4634, -13.1714)
  line L23 (-2.9721, -12.4809) -> (-3.1112, -12.416)
  line L24 (-2.971, -12.4785) -> (-2.9721, -12.4809)
  line L25 (-2.9233, -13.3152) -> (-2.8483, -13.1546)
  line L26 (-3.6019, -12.9988) -> (-2.9233, -13.3152)
  line L27 (-3.5269, -12.8381) -> (-3.6019, -12.9988)
  line L28 (-2.8483, -13.1546) -> (-3.5269, -12.8381)
  curve K20 (-3.604, -13.3978) -> (-3.7764, -13.4546)
  curve K21 (-3.3991, -13.4466) -> (-3.604, -13.3978)
  curve K22 (-3.2715, -13.5236) -> (-3.3991, -13.4466)
  curve K23 (-3.1537, -13.634) -> (-3.2715, -13.5236)
  curve K24 (-3.1341, -13.6548) -> (-3.1537, -13.634)
  curve K25 (-3.1182, -13.6769) -> (-3.1341, -13.6548)
  line L29 (-2.7414, -14.1649) -> (-3.1182, -13.6769)
  line L30 (-2.8242, -14.3424) -> (-2.7414, -14.1649)
  line L31 (-3.2599, -13.7742) -> (-2.8242, -14.3424)
  line L32 (-3.2311, -13.7877) -> (-3.2599, -13.7742)
  curve K26 (-3.2015, -13.8744) -> (-3.2311, -13.7877)
  curve K27 (-3.2224, -13.9756) -> (-3.2015, -13.8744)
  curve K28 (-3.3359, -14.1125) -> (-3.2224, -13.9756)
  curve K29 (-3.4992, -14.156) -> (-3.3359, -14.1125)
  curve K30 (-3.6995, -14.1035) -> (-3.4992, -14.156)
  curve K31 (-3.8711, -13.9768) -> (-3.6995, -14.1035)
  curve K32 (-3.9384, -13.8082) -> (-3.8711, -13.9768)
  curve K33 (-3.8964, -13.6117) -> (-3.9384, -13.8082)
  curve K34 (-3.7764, -13.4546) -> (-3.8964, -13.6117)
  curve K35 (-3.6403, -13.9326) -> (-3.7544, -13.8268)
  curve K36 (-3.4704, -13.9564) -> (-3.6403, -13.9326)
  curve K37 (-3.3583, -13.8539) -> (-3.4704, -13.9564)
  curve K38 (-3.3574, -13.7142) -> (-3.3583, -13.8539)
  curve K39 (-3.4871, -13.6041) -> (-3.3574, -13.7142)
  curve K40 (-3.6415, -13.5846) -> (-3.4871, -13.6041)
  curve K41 (-3.7454, -13.6822) -> (-3.6415, -13.5846)
  curve K42 (-3.7544, -13.8268) -> (-3.7454, -13.6822)
  curve K43 (-4.011, -14.2706) -> (-4.1835, -14.3274)
  curve K44 (-3.8061, -14.3195) -> (-4.011, -14.2706)
  curve K45 (-3.6785, -14.3965) -> (-3.8061, -14.3195)
  curve K46 (-3.5607, -14.5069) -> (-3.6785, -14.3965)
  curve K47 (-3.5412, -14.5277) -> (-3.5607, -14.5069)
  curve K48 (-3.5252, -14.5497) -> (-3.5412, -14.5277)
  line L33 (-3.1484, -15.0378) -> (-3.5252, -14.5497)
  line L34 (-3.2312, -15.2152) -> (-3.1484, -15.0378)
  line L35 (-3.6669, -14.6471) -> (-3.2312, -15.2152)
  line L36 (-3.6381, -14.6605) -> (-3.6669, -14.6471)
  curve K49 (-3.6085, -14.7473) -> (-3.6381, -14.6605)
  curve K50 (-3.6295, -14.8485) -> (-3.6085, -14.7473)
  curve K51 (-3.7429, -14.9853) -> (-3.6295, -14.8485)
  curve K52 (-3.9063, -15.0289) -> (-3.7429, -14.9853)
  curve K53 (-4.1065, -14.9763) -> (-3.9063, -15.0289)
  curve K54 (-4.2781, -14.8496) -> (-4.1065, -14.9763)
  curve K55 (-4.3454, -14.681) -> (-4.2781, -14.8496)
  curve K56 (-4.3035, -14.4846) -> (-4.3454, -14.681)
  curve K57 (-4.1835, -14.3274) -> (-4.3035, -14.4846)
  curve K58 (-4.0484, -14.8078) -> (-4.1626, -14.7021)
  curve K59 (-3.8785, -14.8316) -> (-4.0484, -14.8078)
  curve K60 (-3.7665, -14.7291) -> (-3.8785, -14.8316)
  curve K61 (-3.7656, -14.5894) -> (-3.7665, -14.7291)
  curve K62 (-3.8952, -14.4793) -> (-3.7656, -14.5894)
  curve K63 (-4.0496, -14.4599) -> (-3.8952, -14.4793)
  curve K64 (-4.1535, -14.5574) -> (-4.0496, -14.4599)
  curve K65 (-4.1626, -14.7021) -> (-4.1535, -14.5574)
  line L37 (-3.4984, -15.7883) -> (-3.4224, -15.6252)
  line L38 (-4.6518, -15.2505) -> (-3.4984, -15.7883)
  line L39 (-4.5747, -15.085) -> (-4.6518, -15.2505)
  line L40 (-3.4213, -15.6228) -> (-4.5747, -15.085)
  line L41 (-3.4224, -15.6252) -> (-3.4213, -15.6228)
  line L42 (-4.1534, -15.8595) -> (-3.9667, -15.459)
  curve K66 (-4.171, -15.9535) -> (-4.1534, -15.8595)
  curve K67 (-4.1344, -16.0377) -> (-4.171, -15.9535)
  curve K68 (-4.0498, -16.1005) -> (-4.1344, -16.0377)
  curve K69 (-3.9473, -16.1249) -> (-4.0498, -16.1005)
  curve K70 (-3.8593, -16.0988) -> (-3.9473, -16.1249)
  curve K71 (-3.7985, -16.025) -> (-3.8593, -16.0988)
  line L43 (-3.6118, -15.6245) -> (-3.7985, -16.025)
  line L44 (-3.4583, -15.6961) -> (-3.6118, -15.6245)
  line L45 (-3.6428, -16.0917) -> (-3.4583, -15.6961)
  curve K72 (-3.7675, -16.2526) -> (-3.6428, -16.0917)
  curve K73 (-3.9409, -16.3177) -> (-3.7675, -16.2526)
  curve K74 (-4.136, -16.2792) -> (-3.9409, -16.3177)
  curve K75 (-4.291, -16.1544) -> (-4.136, -16.2792)
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extrude "Extrude6" sketch "Sketch13" blind 0.1 (= "d44")
work_plane "WorkPlane9" AlongDistance -24
sketch "GEMFAN (1)" plane through (0, -14, 0) normal (0, 1, 0) x axis (1, 0, 0)
  line L1 (14.7599, 3.57) -> (14.4217, 3.5404)
  line L2 (13.0297, 3.6245) -> (12.5505, 3.5826)
  line L3 (11.4582, 4.1364) -> (11.5325, 3.2871)
  line L4 (13.5386, 3.4654) -> (13.241, 4.2924)
  line L5 (13.7113, 3.9547) -> (13.8768, 3.495)
  line L6 (11.5325, 3.2871) -> (11.8862, 3.318)
  line L7 (10.5733, 4.059) -> (10.1982, 4.0262)
  line L8 (14.0171, 3.9044) -> (14.0175, 4.2254)
  curve K1 (14.5044, 4.4029) -> (14.9547, 4.1811)
  line L9 (12.2546, 3.3502) -> (12.6403, 3.384)
  line L10 (12.0411, 3.6663) -> (11.8484, 3.6494)
  line L11 (11.8214, 3.958) -> (12.0411, 3.6663)
  line L12 (15.6189, 4.0505) -> (15.7617, 3.6697)
  line L13 (10.9828, 3.7) -> (11.1387, 3.2526)
  line L14 (12.0355, 4.1869) -> (11.4582, 4.1364)
  line L15 (11.8484, 3.6494) -> (11.8214, 3.958)
  line L16 (15.0785, 4.0893) -> (15.1571, 4.0961)
  line L17 (13.8768, 3.495) -> (13.5386, 3.4654)
  line L18 (10.8062, 4.0794) -> (10.7407, 3.5783)
  line L19 (14.0506, 3.5102) -> (13.7113, 3.9547)
  line L20 (12.9031, 3.9881) -> (12.4198, 3.9458)
  line L21 (14.672, 4.0543) -> (15.034, 3.9089)
  line L22 (14.4217, 3.5404) -> (14.2558, 4.0243)
  line L23 (15.034, 3.9089) -> (14.7295, 3.8822)
  line L24 (15.5899, 3.6426) -> (14.8317, 3.5762)
  line L25 (15.2208, 3.8324) -> (15.5899, 3.6426)
  line L26 (14.7295, 3.8822) -> (14.672, 4.0543)
  line L27 (10.4874, 3.1956) -> (10.9219, 3.2337)
  line L28 (12.4198, 3.9458) -> (12.3239, 4.2122)
  line L29 (12.938, 3.8912) -> (12.9031, 3.9881)
  line L30 (12.1632, 3.4716) -> (12.2546, 3.3502)
  line L31 (14.8317, 3.5762) -> (14.7596, 3.7921)
  line L32 (12.3239, 4.2122) -> (13.1554, 4.2849)
  line L33 (10.7407, 3.5783) -> (10.5733, 4.059)
  line L34 (11.8862, 3.318) -> (11.8749, 3.4463)
  line L35 (10.9219, 3.2337) -> (10.9828, 3.7)
  line L36 (13.1554, 4.2849) -> (13.454, 3.4552)
  curve K2 (15.0785, 4.0893) -> (15.6833, 3.6662)
  curve K3 (15.7617, 3.6697) -> (15.4751, 4.4516)
  line L37 (15.9662, 4.0809) -> (15.6189, 4.0505)
  curve K4 (9.3781, 4.4194) -> (15.6475, 3.6558)
  curve K5 (9.8193, 4.13) -> (15.6475, 3.6558)
  line L38 (14.5044, 4.4029) -> (15.3814, 4.4797)
  line L39 (10.1982, 4.0262) -> (10.4874, 3.1956)
  line L40 (16.0469, 3.8591) -> (15.9662, 4.0809)
  curve K6 (16.0469, 3.8591) -> (15.5621, 4.21)
  line L41 (13.1018, 3.4244) -> (13.0297, 3.6245)
  line L42 (14.2558, 4.0243) -> (14.2551, 3.5281)
  line L43 (12.4546, 3.8489) -> (12.938, 3.8912)
  line L44 (14.0175, 4.2254) -> (14.585, 4.08)
  line L45 (12.6403, 3.384) -> (12.0355, 4.1869)
  line L46 (14.9547, 4.1811) -> (15.1214, 4.1957)
  line L47 (11.1387, 3.2526) -> (11.4801, 3.2825)
  line L48 (15.1571, 4.0961) -> (15.1214, 4.1957)
  line L49 (11.1908, 4.113) -> (10.8062, 4.0794)
  line L50 (13.454, 3.4552) -> (13.1018, 3.4244)
  line L51 (9.8193, 4.13) -> (9.3781, 4.4194)
  line L52 (15.6833, 3.6662) -> (15.3814, 4.4797)
  line L53 (15.5621, 4.21) -> (15.4751, 4.4516)
  line L54 (12.5505, 3.5826) -> (12.4546, 3.8489)
  line L55 (11.4801, 3.2825) -> (11.1908, 4.113)
  line L56 (13.6526, 4.3284) -> (14.0171, 3.9044)
  line L57 (14.585, 4.08) -> (14.7599, 3.57)
  line L58 (14.7596, 3.7921) -> (15.2208, 3.8324)
  line L59 (11.8749, 3.4463) -> (12.1632, 3.4716)
  line L60 (13.241, 4.2924) -> (13.6526, 4.3284)
  line L61 (14.2551, 3.5281) -> (14.0506, 3.5102)
sketch "51466R" plane through (28.9566, -14, -18.6867) normal (0, 1, 0) x axis (1, 0, 0)
  line L1 (-32.2901, -34.116) -> (-32.2129, -33.9505)
  line L2 (-33.3698, -34.8474) -> (-33.2993, -34.6963)
  curve K1 (-33.4846, -34.0669) -> (-33.2749, -34.118)
  line L3 (-31.8998, -33.2791) -> (-31.8205, -33.1089)
  curve K2 (-33.657, -34.1237) -> (-33.4846, -34.0669)
  line L4 (-33.2596, -34.3295) -> (-33.3555, -34.2848)
  curve K3 (-33.7817, -34.2846) -> (-33.657, -34.1237)
  curve K4 (-32.9774, -34.6508) -> (-33.0276, -34.7209)
  curve K5 (-33.6517, -34.751) -> (-33.7808, -34.6207)
  curve K6 (-33.8265, -34.4622) -> (-33.7817, -34.2846)
  line L5 (-32.2129, -33.9505) -> (-33.3639, -33.4138)
  line L6 (-32.637, -34.4593) -> (-32.4835, -34.5308)
  line L7 (-32.6441, -34.1553) -> (-32.4787, -34.2324)
  curve K7 (-33.6483, -34.4869) -> (-33.5746, -34.5855)
  curve K8 (-33.005, -34.2906) -> (-32.9366, -34.4568)
  curve K9 (-33.3555, -34.2848) -> (-33.5219, -34.2597)
  line L8 (-32.7631, -35.1303) -> (-33.3698, -34.8474)
  curve K10 (-33.1335, -34.4409) -> (-33.2596, -34.3295)
  line L9 (-33.3639, -33.4138) -> (-33.4411, -33.5793)
  line L10 (-33.2749, -34.118) -> (-33.179, -34.1628)
  line L11 (-32.4651, -34.0344) -> (-32.6441, -34.1553)
  line L12 (-32.4787, -34.2324) -> (-32.2901, -34.116)
  line L13 (-33.4411, -33.5793) -> (-32.4651, -34.0344)
  curve K11 (-32.5221, -31.6898) -> (-32.3496, -31.633)
  line L14 (-33.0007, -32.6286) -> (-32.3221, -32.945)
  line L15 (-32.5559, -32.5324) -> (-32.7046, -32.463)
  curve K12 (-32.3114, -32.3836) -> (-32.4524, -32.3354)
  curve K13 (-32.3496, -31.633) -> (-32.1423, -31.683)
  curve K14 (-32.2351, -31.8382) -> (-32.3895, -31.8188)
  line L16 (-33.5746, -34.5855) -> (-33.6517, -34.751)
  curve K15 (-32.1077, -31.9531) -> (-32.2351, -31.8382)
  line L17 (-33.0568, -33.2184) -> (-32.9177, -33.2832)
  curve K16 (-33.1998, -34.6581) -> (-33.1378, -34.5878)
  line L18 (-32.3221, -32.945) -> (-32.2472, -32.7843)
  line L19 (-33.0984, -34.7725) -> (-32.8394, -34.8933)
  line L20 (-32.4835, -34.5308) -> (-32.7631, -35.1303)
  curve K17 (-33.5219, -34.2597) -> (-33.6317, -34.3574)
  line L21 (-32.8243, -33.1079) -> (-32.5559, -32.5324)
  curve K18 (-33.7808, -34.6207) -> (-33.8265, -34.4622)
  curve K19 (-33.2993, -34.6963) -> (-33.1998, -34.6581)
  line L22 (-32.9177, -33.2832) -> (-32.9188, -33.2856)
  line L23 (-32.7046, -32.463) -> (-33.0568, -33.2184)
  curve K20 (-33.1378, -34.5878) -> (-33.1335, -34.4409)
  curve K21 (-33.179, -34.1628) -> (-33.005, -34.2906)
  line L24 (-32.9188, -33.2856) -> (-31.8998, -33.2791)
  curve K22 (-32.9366, -34.4568) -> (-32.9774, -34.6508)
  curve K23 (-33.0276, -34.7209) -> (-33.0984, -34.7725)
  line L25 (-32.8394, -34.8933) -> (-32.637, -34.4593)
  curve K24 (-33.6317, -34.3574) -> (-33.6483, -34.4869)
  line L26 (-31.8205, -33.1089) -> (-32.8243, -33.1079)
  curve K25 (-31.5266, -31.2578) -> (-31.5907, -31.3389)
  curve K26 (-32.3883, -32.1668) -> (-32.2206, -32.1953)
  line L27 (-30.9897, -31.3272) -> (-31.0724, -31.5046)
  curve K27 (-31.827, -30.963) -> (-31.9814, -30.9435)
  line L28 (-32.9258, -32.4679) -> (-33.0007, -32.6286)
  curve K28 (-31.9977, -32.2117) -> (-32.0832, -32.2448)
  curve K29 (-31.9336, -32.1307) -> (-31.9977, -32.2117)
  curve K30 (-31.5907, -31.3389) -> (-31.6762, -31.372)
  curve K31 (-32.1151, -30.817) -> (-31.9426, -30.7602)
  curve K32 (-32.1142, -32.1048) -> (-32.1077, -31.9531)
  curve K33 (-32.1511, -32.4029) -> (-32.3114, -32.3836)
  curve K34 (-32.2818, -31.1684) -> (-32.2386, -30.9754)
  curve K35 (-32.5025, -32.061) -> (-32.3883, -32.1668)
  curve K36 (-30.8377, -30.131) -> (-30.9401, -30.1066)
  curve K37 (-31.9017, -31.9558) -> (-31.9336, -32.1307)
  curve K38 (-31.9426, -30.7602) -> (-31.7353, -30.8102)
  curve K39 (-31.4947, -31.0829) -> (-31.5266, -31.2578)
  curve K40 (-32.0454, -31.4626) -> (-32.2145, -31.337)
  line L29 (-31.0724, -31.5046) -> (-31.6884, -31.5297)
  curve K41 (-32.6456, -31.8483) -> (-32.5221, -31.6898)
  curve K42 (-32.2386, -30.9754) -> (-32.1151, -30.817)
  curve K43 (-32.1226, -32.4045) -> (-32.1511, -32.4029)
  curve K44 (-31.7156, -31.5317) -> (-31.744, -31.5301)
  curve K45 (-30.7165, -30.2781) -> (-30.7531, -30.1938)
  curve K46 (-31.9814, -30.9435) -> (-32.0864, -31.0435)
  curve K47 (-31.0282, -30.1327) -> (-31.0889, -30.2066)
  curve K48 (-30.5397, -30.2496) -> (-30.5828, -30.4484)
  curve K49 (-32.2145, -31.337) -> (-32.2818, -31.1684)
  curve K50 (-30.6013, -30.0749) -> (-30.5397, -30.2496)
  curve K51 (-32.4524, -32.3354) -> (-32.6215, -32.2098)
  curve K52 (-30.7562, -29.9501) -> (-30.6013, -30.0749)
  curve K53 (-32.0864, -31.0435) -> (-32.0944, -31.1857)
  curve K54 (-30.9514, -29.9116) -> (-30.7562, -29.9501)
  curve K55 (-31.9044, -31.5108) -> (-32.0454, -31.4626)
  curve K56 (-31.5663, -30.9298) -> (-31.4947, -31.0829)
  curve K57 (-31.6884, -31.5297) -> (-31.7156, -31.5317)
  curve K58 (-32.6215, -32.2098) -> (-32.6889, -32.0412)
  curve K59 (-31.7353, -30.8102) -> (-31.5663, -30.9298)
  curve K60 (-32.3895, -31.8188) -> (-32.4945, -31.9187)
  line L30 (-31.3967, -32.2) -> (-31.4794, -32.3775)
  line L31 (-30.7673, -30.8441) -> (-30.9208, -30.7725)
  curve K61 (-31.7061, -31.2296) -> (-31.6996, -31.0779)
  line L32 (-32.0832, -32.2448) -> (-32.1119, -32.2314)
  curve K62 (-32.4945, -31.9187) -> (-32.5025, -32.061)
  curve K63 (-32.1423, -31.683) -> (-31.9733, -31.8027)
  curve K64 (-31.744, -31.5301) -> (-31.9044, -31.5108)
  curve K65 (-32.6889, -32.0412) -> (-32.6456, -31.8483)
  line L33 (-31.6762, -31.372) -> (-31.7049, -31.3586)
  curve K66 (-30.734, -30.3721) -> (-30.7165, -30.2781)
  line L34 (-32.1119, -32.2314) -> (-31.3967, -32.2)
  line L35 (-31.7049, -31.3586) -> (-30.9897, -31.3272)
  curve K67 (-31.9733, -31.8027) -> (-31.9017, -31.9558)
  line L36 (-32.2472, -32.7843) -> (-32.9258, -32.4679)
  line L37 (-31.4794, -32.3775) -> (-32.0954, -32.4026)
  curve K68 (-32.2206, -32.1953) -> (-32.1142, -32.1048)
  curve K69 (-32.0954, -32.4026) -> (-32.1226, -32.4045)
  curve K70 (-31.8125, -31.3201) -> (-31.7061, -31.2296)
  line L38 (-30.7224, -30.7541) -> (-31.8758, -30.2162)
  line L39 (-31.0889, -30.2066) -> (-31.2757, -30.607)
  line L40 (-31.953, -30.3817) -> (-30.7996, -30.9195)
  curve K71 (-30.7531, -30.1938) -> (-30.8377, -30.131)
  line L41 (-31.6431, -29.7234) -> (-31.2444, -30.2333)
  line L42 (-31.2444, -30.2333) -> (-31.1324, -30.087)
  curve K72 (-31.6996, -31.0779) -> (-31.827, -30.963)
  line L43 (-30.7984, -30.9171) -> (-30.7224, -30.7541)
  line L44 (-30.5828, -30.4484) -> (-30.7673, -30.8441)
  line L45 (-31.5514, -29.5267) -> (-31.6431, -29.7234)
  curve K73 (-31.9802, -31.2915) -> (-31.8125, -31.3201)
  line L46 (-31.4328, -30.5308) -> (-31.2483, -30.1352)
  line L47 (-30.9208, -30.7725) -> (-30.734, -30.3721)
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extrude "Extrude7" sketch "GEMFAN (1)" blind -0.1 (= "-d44")
extrude "Extrude8" sketch "51466R" blind -0.1 (= "-d44")
component_from_bodies "Body->Comp1"
component_from_bodies "Body->Comp2"
copy_paste_bodies "CutPasteBodies1"
copy_paste_bodies "CutPasteBodies2"
position "Position1"
copy_paste_bodies "CopyPasteBodies3"
component_from_bodies "Body->Comp1"
copy_paste_bodies "CutPasteBodies1"
component_from_bodies "Body->Comp2"
copy_paste_bodies "CopyPasteBodies2"
component_from_bodies "Body->Comp1"
copy_paste_bodies "CutPasteBodies1"
component_from_bodies "Body->Comp2"
move "Move1"
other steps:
base_feature "Base Feature1" bodies "CCW Prop"
base_feature "Base Feature1" bodies "CW Prop"
base_feature "Base Feature2" bodies "Spin Trail"
base_feature "Base Feature2" bodies "Spin Trail"
base_feature "Base Feature1" bodies "CCW Prop (1)"
base_feature "Base Feature1" bodies "CW Prop (1)"
base_feature "Base Feature1" bodies "CW Prop"
base_feature "Base Feature3" bodies "Spin Trail"
base_feature "Base Feature1" bodies "CCW Prop"
base_feature "Base Feature4" bodies "CW Prop", "CW Prop (1)"
base_feature "Base Feature2" bodies "Spin Trail"
base_feature "Base Feature3" bodies "CCW Prop", "CCW Prop (1)"
create_component "CreateComponent1"
create_component "CreateComponent2"
remove_body "RemoveBody2"
remove_body "RemoveBody3"
remove_body "RemoveBody5"
remove_body "RemoveBody6"
create_component "CreateComponent1"
remove_body "RemoveBody1"
remove_body "RemoveBody2"
create_component "CreateComponent2"
remove_body "RemoveBody3"
create_component "CreateComponent1"
remove_body "RemoveBody1"
remove_body "RemoveBody2"
create_component "CreateComponent2"
remove_body "RemoveBody3"
named bodies: "CW Prop", "CCW Prop", "Spin Trail", "CW Prop (1)", "CCW Prop (1)"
